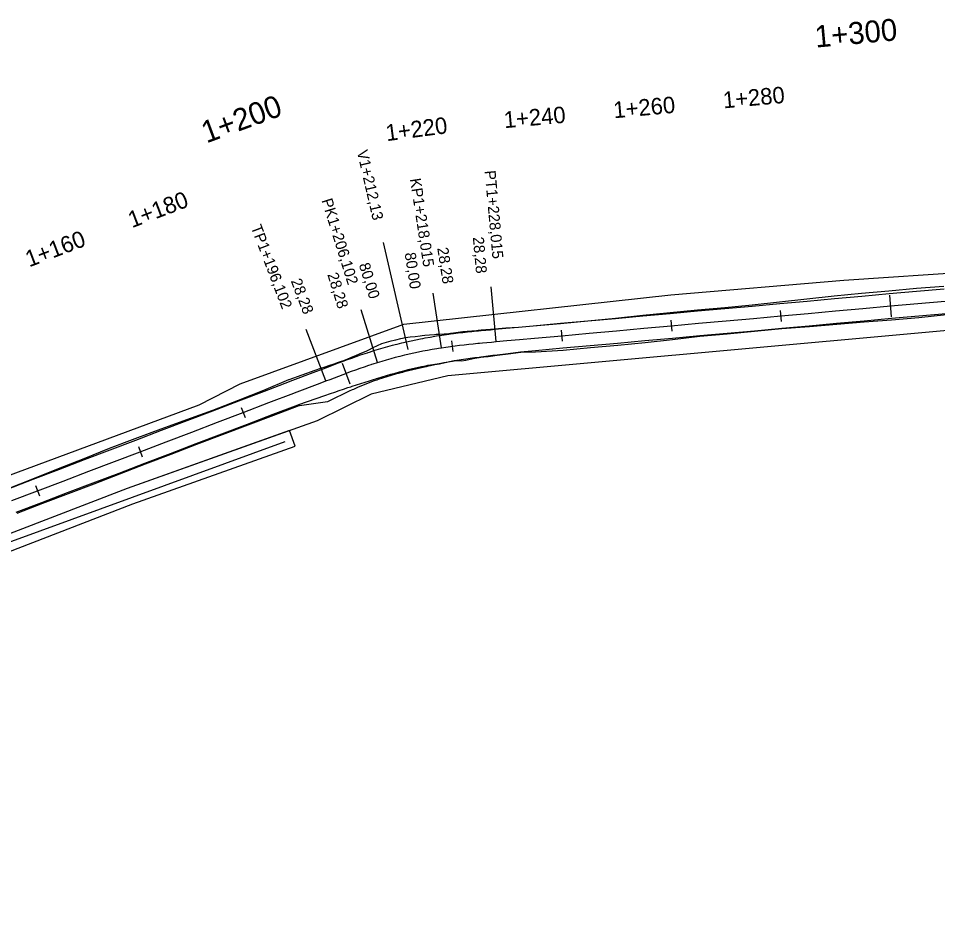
# Model space of a CAD drawing. Extents: x -636600 to -628587, y -1090963 to -1085869.
# Drawn here: x -634173.7 to -634006.6, y -1089706 to -1089541.6 of the extents above; entities that cross this region are included whole.
import ezdxf

# ---------------------------------------------------------------- set-up
doc = ezdxf.new("R2010")
doc.units = 0
for name, color, linetype in [('01_PARCELY_NÁVRH_PC', 7, 'Continuous'), ('06_ÚSES_IP_NAVRH', 7, 'Continuous'), ('HEKTOMETRY100', 7, 'Continuous'), ('HEKTOMETRY20', 7, 'Continuous'), ('HL_BODY', 7, 'Continuous'), ('POLOMERY', 7, 'Continuous'), ('situace_osa', 7, 'Continuous'), ('situace_těleso', 7, 'Continuous'), ('situace_vozovka', 7, 'Continuous'), ('VRCHOLY', 7, 'Continuous')]:
    doc.layers.add(name, color=color, linetype=linetype)

msp = doc.modelspace()

# ---------------------------------------------------------------- linework, layer by layer
at = {"layer": '01_PARCELY_NÁVRH_PC'}
for points in [[(-634431.43, -1089704.66), (-634389.8, -1089674.12), (-634343.84, -1089646.78), (-634333.24, -1089642.69), (-634321.7, -1089640.37), (-634241.91, -1089638.25), (-634196.34, -1089632.38), (-634140.85, -1089611.84), (-634133.43, -1089607.99), (-634103.65, -1089597.17), (-634055.12, -1089591.81), (-634023.67, -1089589.12), (-634000.19, -1089587.56)], [(-633985.38, -1089596.54), (-634095.63, -1089606.53), (-634109.59, -1089609.87), (-634119.39, -1089614.71), (-634153.94, -1089627.03), (-634181.23, -1089637.49), (-634202.3, -1089643.64), (-634215.89, -1089645.05), (-634331.8, -1089648.15), (-634341.16, -1089651.61), (-634353.24, -1089657.77), (-634389.23, -1089679.76), (-634412.34, -1089696.86), (-634425.28, -1089705.95)]]:
    msp.add_lwpolyline(points, dxfattribs=at)
msp.add_lwpolyline([(-634241.21, -1089648.73), (-634215.69, -1089648.05), (-634201.72, -1089646.6), (-634180.27, -1089640.34), (-634152.9, -1089629.84), (-634123.42, -1089619.33), (-634124.43, -1089616.51), (-634153.94, -1089627.03), (-634181.23, -1089637.49), (-634202.3, -1089643.64), (-634215.89, -1089645.05), (-634239.18, -1089645.67)], close=True, dxfattribs=at)
at = {"layer": '06_ÚSES_IP_NAVRH'}
msp.add_lwpolyline([(-634237.23, -1089647.3), (-634202.07, -1089645.3), (-634180.78, -1089638.73), (-634125.21, -1089618.48)], dxfattribs=at)
at = {"layer": 'HEKTOMETRY100'}
for points in [[(-634015.37, -1089591.85), (-634015.01, -1089595.83)], [(-634114.88, -1089604.22), (-634113.49, -1089607.97)]]:
    msp.add_lwpolyline(points, dxfattribs=at)
at = {"layer": 'HEKTOMETRY20'}
for points in [[(-634035.2, -1089594.65), (-634035.02, -1089596.64)], [(-634055.12, -1089596.45), (-634054.94, -1089598.44)], [(-634075.04, -1089598.25), (-634074.86, -1089600.24)], [(-634094.98, -1089600.16), (-634094.72, -1089602.14)], [(-634133.23, -1089612.27), (-634132.52, -1089614.14)], [(-634151.92, -1089619.39), (-634151.21, -1089621.26)], [(-634170.61, -1089626.51), (-634169.9, -1089628.38)]]:
    msp.add_lwpolyline(points, dxfattribs=at)
at = {"layer": 'HL_BODY'}
for points in [[(-634096.82, -1089601.43), (-634098.34, -1089591.54)], [(-634086.88, -1089600.32), (-634087.78, -1089590.36)], [(-634108.41, -1089604.11), (-634111.38, -1089594.56)], [(-634117.83, -1089607.47), (-634121.39, -1089598.13)]]:
    msp.add_lwpolyline(points, dxfattribs=at)
at = {"layer": 'POLOMERY'}
for points in [[(-634096.82, -1089601.43), (-634098.34, -1089591.54)], [(-634086.88, -1089600.32), (-634087.78, -1089590.36)], [(-634108.41, -1089604.11), (-634111.38, -1089594.56)], [(-634117.83, -1089607.47), (-634121.39, -1089598.13)]]:
    msp.add_lwpolyline(points, dxfattribs=at)
at = {"layer": 'situace_osa'}
msp.add_lwpolyline([(-634174.93, -1089629.23), (-634170.26, -1089627.45), (-634165.58, -1089625.67), (-634160.91, -1089623.89), (-634156.24, -1089622.11), (-634151.57, -1089620.33), (-634146.89, -1089618.55), (-634142.22, -1089616.77), (-634137.55, -1089614.98), (-634132.88, -1089613.2), (-634128.2, -1089611.42), (-634123.64, -1089609.68), (-634123.53, -1089609.64), (-634118.86, -1089607.86), (-634117.83, -1089607.47), (-634117.05, -1089607.18), (-634116.27, -1089606.88), (-634115.49, -1089606.58), (-634114.71, -1089606.29), (-634114.18, -1089606.1), (-634113.93, -1089606), (-634113.15, -1089605.72), (-634112.36, -1089605.43), (-634111.58, -1089605.16), (-634110.79, -1089604.88), (-634110, -1089604.62), (-634109.57, -1089604.48), (-634109.46, -1089604.44), (-634109.21, -1089604.36), (-634108.41, -1089604.11), (-634107.6, -1089603.86), (-634106.78, -1089603.62), (-634105.97, -1089603.39), (-634105.14, -1089603.17), (-634104.67, -1089603.04), (-634104.32, -1089602.95), (-634103.49, -1089602.75), (-634102.67, -1089602.55), (-634101.84, -1089602.36), (-634101, -1089602.19), (-634100.17, -1089602.02), (-634099.79, -1089601.94), (-634099.33, -1089601.86), (-634098.5, -1089601.7), (-634097.66, -1089601.56), (-634097.37, -1089601.51), (-634096.82, -1089601.43), (-634095.99, -1089601.31), (-634095.17, -1089601.19), (-634094.85, -1089601.15), (-634094.34, -1089601.08), (-634093.51, -1089600.98), (-634092.69, -1089600.89), (-634091.86, -1089600.8), (-634091.03, -1089600.71), (-634090.2, -1089600.63), (-634089.88, -1089600.6), (-634089.37, -1089600.55), (-634088.54, -1089600.47), (-634087.71, -1089600.4), (-634086.88, -1089600.32), (-634084.9, -1089600.14), (-634082.62, -1089599.94), (-634079.92, -1089599.69), (-634074.95, -1089599.24), (-634069.97, -1089598.79), (-634064.99, -1089598.34), (-634060.01, -1089597.89), (-634055.03, -1089597.44), (-634050.05, -1089596.99), (-634045.07, -1089596.54), (-634040.09, -1089596.09), (-634035.11, -1089595.64), (-634030.13, -1089595.19), (-634025.15, -1089594.74), (-634020.17, -1089594.29), (-634015.19, -1089593.84), (-634010.21, -1089593.39), (-634005.23, -1089592.94)], dxfattribs=at)
at = {"layer": 'situace_těleso'}
for points in [[(-634175.74, -1089627.08), (-634171.1, -1089625.24), (-634166.45, -1089623.39), (-634161.8, -1089621.55), (-634157.15, -1089619.7), (-634152.48, -1089617.92), (-634147.8, -1089616.16), (-634143.08, -1089614.51), (-634138.38, -1089612.79), (-634133.73, -1089610.97), (-634129.08, -1089609.12), (-634124.57, -1089607.23), (-634124.47, -1089607.19), (-634119.76, -1089605.5), (-634118.72, -1089605.14), (-634117.93, -1089604.88), (-634117.13, -1089604.61), (-634116.34, -1089604.34), (-634115.54, -1089604.08), (-634115, -1089603.9), (-634114.74, -1089603.81), (-634113.94, -1089603.54), (-634113.17, -1089603.17), (-634112.4, -1089602.82), (-634111.61, -1089602.49), (-634110.81, -1089602.18), (-634110.38, -1089602.02), (-634110.27, -1089601.96), (-634110.03, -1089601.82), (-634109.25, -1089601.41), (-634108.45, -1089601.03), (-634107.63, -1089600.69), (-634106.78, -1089600.44), (-634105.93, -1089600.2), (-634105.43, -1089600.07), (-634105.08, -1089599.97), (-634104.22, -1089599.74), (-634103.36, -1089599.56), (-634102.47, -1089599.46), (-634101.59, -1089599.4), (-634100.71, -1089599.29), (-634100.31, -1089599.23), (-634099.84, -1089599.17), (-634098.96, -1089599.07), (-634098.08, -1089599), (-634097.77, -1089598.98), (-634097.2, -1089598.95), (-634096.34, -1089598.92), (-634095.49, -1089598.83), (-634095.16, -1089598.79), (-634094.64, -1089598.72), (-634093.8, -1089598.61), (-634092.95, -1089598.51), (-634092.11, -1089598.41), (-634091.27, -1089598.33), (-634090.43, -1089598.27), (-634090.11, -1089598.24), (-634089.59, -1089598.2), (-634088.76, -1089598.13), (-634087.92, -1089598.07), (-634087.09, -1089598), (-634085.11, -1089597.84), (-634082.82, -1089597.67), (-634080.13, -1089597.45), (-634075.15, -1089596.98), (-634070.17, -1089596.53), (-634065.19, -1089596.05), (-634060.22, -1089595.53), (-634055.24, -1089595.03), (-634050.27, -1089594.56), (-634045.29, -1089594.09), (-634040.31, -1089593.63), (-634035.34, -1089593.09), (-634030.37, -1089592.53), (-634025.4, -1089591.97), (-634020.42, -1089591.5), (-634015.44, -1089591.06), (-634010.46, -1089590.62), (-634005.48, -1089590.22)], [(-634005, -1089595.47), (-634009.98, -1089595.97), (-634014.96, -1089596.42), (-634019.94, -1089596.81), (-634024.92, -1089597.21), (-634029.91, -1089597.61), (-634034.89, -1089598.01), (-634039.87, -1089598.48), (-634044.85, -1089598.95), (-634049.83, -1089599.41), (-634054.79, -1089600.02), (-634059.77, -1089600.54), (-634064.74, -1089601.03), (-634069.72, -1089601.48), (-634074.7, -1089601.92), (-634079.7, -1089602.21), (-634082.4, -1089602.31), (-634084.68, -1089602.6), (-634086.65, -1089602.85), (-634087.48, -1089602.95), (-634088.3, -1089603.06), (-634089.12, -1089603.16), (-634089.63, -1089603.23), (-634089.94, -1089603.27), (-634090.76, -1089603.39), (-634091.57, -1089603.56), (-634092.37, -1089603.73), (-634093.17, -1089603.86), (-634094, -1089603.82), (-634094.5, -1089603.87), (-634094.8, -1089603.93), (-634095.59, -1089604.08), (-634096.39, -1089604.24), (-634096.91, -1089604.35), (-634097.19, -1089604.4), (-634098, -1089604.55), (-634098.8, -1089604.71), (-634099.24, -1089604.8), (-634099.6, -1089604.88), (-634100.41, -1089605.06), (-634101.2, -1089605.24), (-634102, -1089605.43), (-634102.8, -1089605.62), (-634103.59, -1089605.82), (-634103.92, -1089605.91), (-634104.38, -1089606.03), (-634105.17, -1089606.25), (-634105.96, -1089606.48), (-634106.74, -1089606.72), (-634107.53, -1089606.97), (-634108.29, -1089607.22), (-634108.53, -1089607.3), (-634108.64, -1089607.33), (-634109.06, -1089607.46), (-634109.82, -1089607.73), (-634110.57, -1089608.05), (-634111.32, -1089608.35), (-634112.08, -1089608.67), (-634112.83, -1089609), (-634113.07, -1089609.11), (-634113.57, -1089609.34), (-634114.32, -1089609.69), (-634115.07, -1089610.05), (-634115.82, -1089610.41), (-634116.57, -1089610.78), (-634117.56, -1089611.26), (-634122.64, -1089611.98), (-634122.75, -1089612.01), (-634127.33, -1089613.73), (-634132, -1089615.5), (-634136.68, -1089617.26), (-634141.35, -1089619.05), (-634146.02, -1089620.84), (-634150.69, -1089622.63), (-634155.36, -1089624.42), (-634160.03, -1089626.21), (-634164.7, -1089628), (-634169.36, -1089629.78), (-634174.03, -1089631.57)]]:
    msp.add_lwpolyline(points, dxfattribs=at)
at = {"layer": 'situace_vozovka'}
for points in [[(-634175.73, -1089627.12), (-634171.06, -1089625.34), (-634166.38, -1089623.56), (-634161.71, -1089621.78), (-634157.04, -1089620), (-634152.37, -1089618.22), (-634147.69, -1089616.44), (-634143.02, -1089614.66), (-634138.35, -1089612.88), (-634133.68, -1089611.1), (-634129.01, -1089609.32), (-634124.44, -1089607.58), (-634124.33, -1089607.54), (-634119.66, -1089605.76), (-634118.63, -1089605.37), (-634117.85, -1089605.07), (-634117.07, -1089604.78), (-634116.29, -1089604.48), (-634115.5, -1089604.18), (-634114.96, -1089603.99), (-634114.71, -1089603.89), (-634113.92, -1089603.6), (-634113.12, -1089603.31), (-634112.32, -1089603.03), (-634111.52, -1089602.75), (-634110.71, -1089602.48), (-634110.27, -1089602.34), (-634110.16, -1089602.3), (-634109.9, -1089602.22), (-634109.08, -1089601.96), (-634108.25, -1089601.7), (-634107.41, -1089601.46), (-634106.56, -1089601.22), (-634105.72, -1089600.99), (-634105.23, -1089600.86), (-634104.87, -1089600.77), (-634104.02, -1089600.56), (-634103.17, -1089600.36), (-634102.32, -1089600.17), (-634101.46, -1089599.98), (-634100.61, -1089599.81), (-634100.21, -1089599.73), (-634099.75, -1089599.64), (-634098.89, -1089599.49), (-634098.02, -1089599.34), (-634097.72, -1089599.29), (-634097.16, -1089599.2), (-634096.31, -1089599.08), (-634095.47, -1089598.96), (-634095.15, -1089598.92), (-634094.62, -1089598.85), (-634093.78, -1089598.75), (-634092.94, -1089598.65), (-634092.1, -1089598.56), (-634091.26, -1089598.47), (-634090.42, -1089598.39), (-634090.1, -1089598.36), (-634089.58, -1089598.31), (-634088.75, -1089598.23), (-634087.91, -1089598.16), (-634087.08, -1089598.08), (-634085.11, -1089597.9), (-634082.82, -1089597.69), (-634080.13, -1089597.45), (-634075.15, -1089597), (-634070.17, -1089596.55), (-634065.19, -1089596.1), (-634060.21, -1089595.65), (-634055.23, -1089595.2), (-634050.25, -1089594.75), (-634045.27, -1089594.3), (-634040.29, -1089593.85), (-634035.31, -1089593.4), (-634030.33, -1089592.95), (-634025.35, -1089592.5), (-634020.37, -1089592.05), (-634015.39, -1089591.6), (-634010.41, -1089591.15), (-634005.43, -1089590.7)], [(-634174.13, -1089631.33), (-634169.45, -1089629.55), (-634164.78, -1089627.77), (-634160.11, -1089625.99), (-634155.44, -1089624.21), (-634150.77, -1089622.43), (-634146.09, -1089620.65), (-634141.42, -1089618.87), (-634136.75, -1089617.09), (-634132.08, -1089615.31), (-634127.4, -1089613.53), (-634122.84, -1089611.79), (-634122.73, -1089611.75), (-634118, -1089610.12), (-634116.96, -1089609.76), (-634116.17, -1089609.49), (-634115.38, -1089609.22), (-634114.6, -1089608.96), (-634113.82, -1089608.69), (-634113.29, -1089608.52), (-634113.04, -1089608.43), (-634112.26, -1089608.18), (-634111.48, -1089607.92), (-634110.7, -1089607.68), (-634109.92, -1089607.44), (-634109.14, -1089607.2), (-634108.72, -1089607.08), (-634108.62, -1089607.05), (-634108.37, -1089606.97), (-634107.6, -1089606.72), (-634106.81, -1089606.48), (-634106.03, -1089606.25), (-634105.24, -1089606.03), (-634104.44, -1089605.81), (-634103.98, -1089605.69), (-634103.65, -1089605.61), (-634102.85, -1089605.41), (-634102.05, -1089605.22), (-634101.25, -1089605.04), (-634100.44, -1089604.87), (-634099.64, -1089604.7), (-634099.27, -1089604.63), (-634098.83, -1089604.55), (-634098.02, -1089604.4), (-634097.21, -1089604.27), (-634096.93, -1089604.22), (-634096.4, -1089604.12), (-634095.61, -1089603.97), (-634094.81, -1089603.83), (-634094.51, -1089603.78), (-634094.01, -1089603.7), (-634093.21, -1089603.58), (-634092.4, -1089603.46), (-634091.59, -1089603.34), (-634090.77, -1089603.23), (-634089.96, -1089603.12), (-634089.65, -1089603.08), (-634089.14, -1089603.01), (-634088.32, -1089602.91), (-634087.49, -1089602.81), (-634086.67, -1089602.7), (-634084.7, -1089602.46), (-634082.41, -1089602.18), (-634079.72, -1089601.93), (-634074.74, -1089601.48), (-634069.76, -1089601.03), (-634064.78, -1089600.58), (-634059.8, -1089600.13), (-634054.82, -1089599.68), (-634049.84, -1089599.23), (-634044.86, -1089598.78), (-634039.88, -1089598.33), (-634034.9, -1089597.88), (-634029.93, -1089597.43), (-634024.95, -1089596.98), (-634019.97, -1089596.53), (-634014.99, -1089596.08), (-634010.01, -1089595.63), (-634005.03, -1089595.18)]]:
    msp.add_lwpolyline(points, dxfattribs=at)
at = {"layer": 'VRCHOLY'}
msp.add_lwpolyline([(-634102.85, -1089601.76), (-634107.35, -1089582.28)], dxfattribs=at)

# ---------------------------------------------------------------- texts
at = {"layer": 'HEKTOMETRY100'}
for s, rotation, p in [('1+300', 5.1631, (-634028.75, -1089546.87)), ('1+200', 20.3132, (-634139.54, -1089564.3))]:
    msp.add_text(s, height=4, rotation=rotation, dxfattribs=at).set_placement(p)
at = {"layer": 'HEKTOMETRY20'}
for s, rotation, p in [('1+280', 5.1631, (-634045.5, -1089557.92)), ('1+260', 5.1631, (-634065.42, -1089559.72)), ('1+240', 5.1631, (-634085.34, -1089561.52)), ('1+220', 7.4636, (-634106.75, -1089563.88)), ('1+180', 20.8573, (-634153.08, -1089579.7)), ('1+160', 20.8573, (-634171.77, -1089586.83))]:
    msp.add_text(s, height=3, rotation=rotation, dxfattribs=at).set_placement(p)
at = {"layer": 'HL_BODY'}
for s, rotation, p in [('PT1+228,015', 275.1631, (-634088.97, -1089569.27)), ('KP1+218,015', 278.7441, (-634102.55, -1089570.76)), ('PK1+206,102', 287.2763, (-634118.63, -1089574.63)), ('TP1+196,102', 290.8573, (-634131.5, -1089579.51))]:
    msp.add_text(s, height=2, rotation=rotation, dxfattribs=at).set_placement(p)
at = {"layer": 'POLOMERY'}
for s, rotation, p in [('28,28', 275.1631, (-634091.11, -1089581.35)), ('28,28', 278.7441, (-634097.58, -1089583.33)), ('80,00', 278.7441, (-634103.51, -1089584.25)), ('80,00', 287.2763, (-634111.85, -1089586.33)), ('28,28', 287.2763, (-634117.58, -1089588.11)), ('28,28', 290.8573, (-634124.23, -1089589.28))]:
    msp.add_text(s, height=2, rotation=rotation, dxfattribs=at).set_placement(p)
at = {"layer": 'VRCHOLY'}
msp.add_text('V1+212,13', height=2, rotation=283.0102, dxfattribs=at).set_placement((-634112.2, -1089565.73))

doc.saveas('drawing.dxf')
